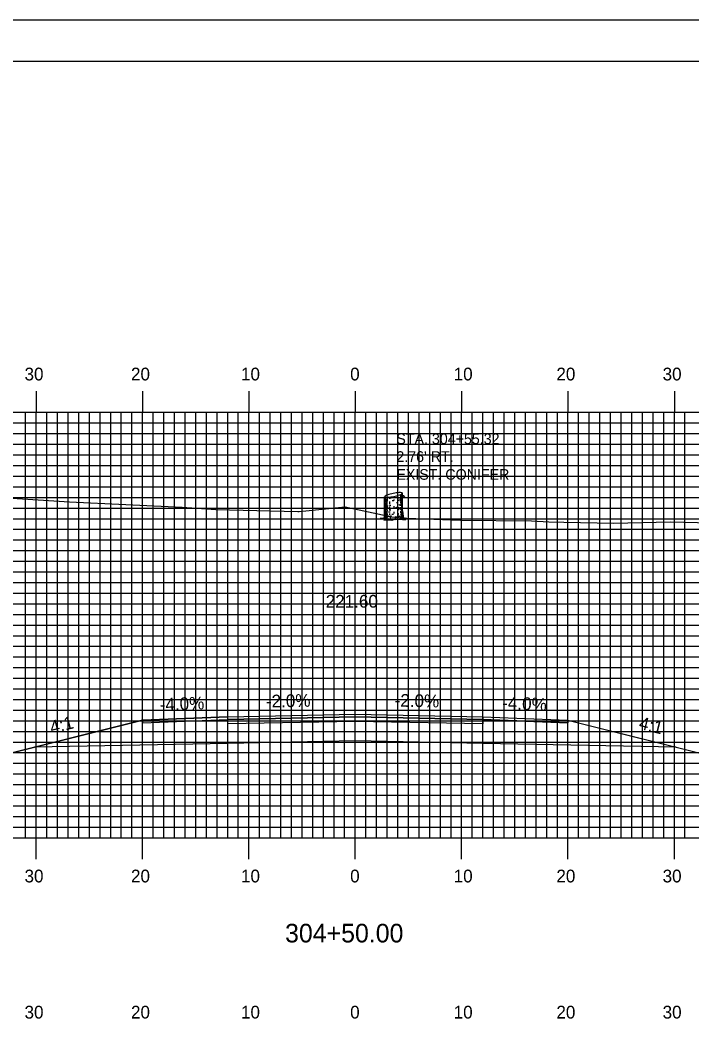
# Model space of a CAD drawing. Extents: x 1816489 to 1816833, y 442591 to 442811.
# Drawn here: x 1816623.6 to 1816686.7, y 442716.2 to 442810.5 of the extents above; entities that cross this region are included whole.
import ezdxf

# ---------------------------------------------------------------- set-up
doc = ezdxf.new("R2010")
doc.units = 0
for name, color, linetype in [('ANNOTATION', 7, 'Continuous'), ('BORDER', 7, 'Continuous'), ('D_Roadway_Centerline', 7, 'Continuous'), ('D_Roadway_Centerline_Text', 7, 'Continuous'), ('D_Roadway_Edge_Shoulder', 7, 'Continuous'), ('D_Roadway_Edge_TW', 7, 'Continuous'), ('D_Roadway_Pavement', 7, 'Continuous'), ('D_Roadway_SlopeLines', 7, 'Continuous'), ('D_Roadway_SubGrade', 7, 'Continuous'), ('D_Text_Monospaced', 7, 'Continuous'), ('H_V ANNOTATION', 7, 'Continuous'), ('M_Trees_Conifer_Pay', 7, 'Continuous'), ('MAJOR', 7, 'Continuous'), ('MINOR', 7, 'Continuous'), ('PLOT BOUNDARY', 7, 'Continuous'), ('S_Roadway_Centerline', 7, 'Continuous')]:
    doc.layers.add(name, color=color, linetype=linetype)

msp = doc.modelspace()

# ---------------------------------------------------------------- linework, layer by layer
at = {"layer": 'BORDER'}
msp.add_lwpolyline([(1816505.473, 442596.665), (1816825.473, 442596.665), (1816825.473, 442806.665), (1816505.473, 442806.665)], close=True, dxfattribs=at)
at = {"layer": 'D_Roadway_Centerline'}
msp.add_lwpolyline([(1816567.063, 442766.87), (1816568.313, 442766.776), (1816569.563, 442766.53), (1816570.813, 442766.133), (1816572.063, 442765.584), (1816620.899, 442741.166), (1816624.899, 442742.166), (1816635.073, 442744.709), (1816643.073, 442745.029), (1816655.073, 442745.269), (1816667.073, 442745.029), (1816675.073, 442744.709), (1816685.247, 442742.166), (1816689.247, 442741.166), (1816725.957, 442759.521), (1816727.207, 442760.056), (1816728.457, 442760.411), (1816729.707, 442760.586), (1816730.957, 442760.58)], dxfattribs=at)
at = {"layer": 'D_Roadway_Edge_Shoulder'}
for points in [[(1816643.073, 442745.029), (1816635.073, 442744.709), (1816635.073, 442744.459), (1816643.073, 442744.779)], [(1816667.073, 442745.029), (1816675.073, 442744.709), (1816675.073, 442744.459), (1816667.073, 442744.779)]]:
    msp.add_lwpolyline(points, close=True, dxfattribs=at)
at = {"layer": 'D_Roadway_Edge_TW'}
msp.add_lwpolyline([(1816643.073, 442744.779), (1816643.073, 442745.029), (1816655.073, 442745.269), (1816667.073, 442745.029), (1816667.073, 442744.779), (1816655.073, 442745.019)], close=True, dxfattribs=at)
at = {"layer": 'D_Roadway_Pavement'}
msp.add_lwpolyline([(1816643.073, 442744.362), (1816643.073, 442744.779), (1816655.073, 442745.019), (1816667.073, 442744.779), (1816667.073, 442744.362), (1816655.073, 442744.602)], close=True, dxfattribs=at)
at = {"layer": 'D_Roadway_SlopeLines'}
for points in [[(1816635.073, 442744.709), (1816620.899, 442741.166)], [(1816675.073, 442744.709), (1816689.247, 442741.166)]]:
    msp.add_lwpolyline(points, dxfattribs=at)
at = {"layer": 'D_Roadway_SubGrade'}
msp.add_lwpolyline([(1816643.073, 442742.529), (1816624.899, 442742.166), (1816635.073, 442744.709), (1816635.073, 442744.459), (1816643.073, 442744.779), (1816655.073, 442745.019), (1816667.073, 442744.779), (1816675.073, 442744.459), (1816675.073, 442744.709), (1816685.247, 442742.166), (1816667.073, 442742.529), (1816655.073, 442742.769)], close=True, dxfattribs=at)
at = {"layer": 'M_Trees_Conifer_Pay'}
for p, q in [((1816659.309, 442765.928), (1816659.309, 442765.705)), ((1816659.426, 442765.989), (1816659.426, 442765.827)), ((1816659.426, 442765.759), (1816659.426, 442765.631)), ((1816659.498, 442764.415), (1816659.498, 442766.062)), ((1816657.834, 442764.005), (1816657.834, 442765.726)), ((1816657.881, 442765.689), (1816657.881, 442765.218)), ((1816657.881, 442765.153), (1816657.881, 442764.845)), ((1816657.939, 442765.678), (1816657.939, 442765.58)), ((1816657.939, 442765.506), (1816657.939, 442765.302)), ((1816657.939, 442765.244), (1816657.939, 442765.045)), ((1816657.939, 442764.997), (1816657.939, 442764.661)), ((1816658.065, 442765.67), (1816658.065, 442765.438)), ((1816658.065, 442765.397), (1816658.065, 442765.323)), ((1816658.065, 442764.919), (1816658.065, 442764.781)), ((1816658.284, 442765.69), (1816658.284, 442765.522)), ((1816658.284, 442765.285), (1816658.284, 442765.048)), ((1816658.69, 442765.459), (1816658.69, 442765.363)), ((1816658.69, 442764.845), (1816658.69, 442764.771)), ((1816659.08, 442765.732), (1816659.08, 442765.533)), ((1816659.08, 442765.475), (1816659.08, 442765.386)), ((1816659.08, 442765.039), (1816659.08, 442764.934)), ((1816659.309, 442765.617), (1816659.309, 442765.569)), ((1816659.309, 442765.234), (1816659.309, 442765.102)), ((1816659.309, 442764.991), (1816659.309, 442764.882)), ((1816659.366, 442765.434), (1816659.315, 442765.374)), ((1816659.426, 442765.444), (1816659.426, 442765.108)), ((1816659.426, 442765.071), (1816659.426, 442764.909)), ((1816659.426, 442764.861), (1816659.426, 442764.645)), ((1816657.881, 442764.798), (1816657.881, 442764.306)), ((1816657.881, 442764.252), (1816657.881, 442764.005)), ((1816657.939, 442764.608), (1816657.939, 442764.472)), ((1816657.939, 442764.373), (1816657.939, 442763.995)), ((1816658.065, 442764.509), (1816658.065, 442764.367)), ((1816658.065, 442764.106), (1816658.065, 442764.011)), ((1816658.284, 442764.804), (1816658.284, 442764.651)), ((1816658.284, 442764.608), (1816658.284, 442764.435)), ((1816658.284, 442764.157), (1816658.284, 442764.005)), ((1816658.69, 442764.746), (1816658.69, 442764.598)), ((1816658.69, 442764.306), (1816658.69, 442764.153)), ((1816659.08, 442764.567), (1816659.08, 442764.421)), ((1816659.08, 442764.188), (1816659.08, 442764.1)), ((1816659.309, 442764.746), (1816659.309, 442764.604)), ((1816659.309, 442764.377), (1816659.309, 442764.205)), ((1816659.426, 442764.614), (1816659.426, 442764.54)), ((1816659.426, 442764.499), (1816659.426, 442764.326)), ((1816658.065, 442763.611), (1816658.227, 442763.675)), ((1816658.502, 442763.547), (1816658.376, 442763.611))]:
    msp.add_line(p, q, dxfattribs=at)
for points in [[(1816659.315, 442765.56), (1816659.351, 442765.485), (1816659.399, 442765.543), (1816659.456, 442765.611), (1816659.549, 442765.804), (1816659.613, 442765.852), (1816659.644, 442765.858)], [(1816659.329, 442765.306), (1816659.366, 442765.434), (1816659.429, 442765.549), (1816659.46, 442765.617), (1816659.529, 442765.763)], [(1816659.544, 442765.793), (1816659.619, 442765.8), (1816659.691, 442765.701)], [(1816658.013, 442765.032), (1816658.007, 442765.127), (1816658.05, 442765.104), (1816658.05, 442765.01)], [(1816659.281, 442765.522), (1816659.25, 442765.438), (1816659.246, 442765.37), (1816659.277, 442765.306)], [(1816659.498, 442764.415), (1816659.549, 442764.153), (1816659.565, 442763.879), (1816659.623, 442763.754), (1816659.759, 442763.723), (1816659.528, 442763.686), (1816659.528, 442763.686), (1816659.534, 442763.638), (1816659.782, 442763.544), (1816659.507, 442763.56), (1816659.152, 442763.581), (1816658.83, 442763.57), (1816658.837, 442763.653), (1816658.689, 442763.57), (1816658.502, 442763.547), (1816658.526, 442763.48), (1816658.258, 442763.523), (1816658.038, 442763.496), (1816657.745, 442763.513), (1816658.034, 442763.57), (1816658.065, 442763.611), (1816657.902, 442763.669), (1816657.665, 442763.68), (1816657.424, 442763.68), (1816657.766, 442763.737), (1816657.807, 442763.818), (1816657.834, 442764.005)], [(1816657.882, 442763.957), (1816657.861, 442763.879), (1816657.84, 442763.785)], [(1816657.96, 442763.937), (1816657.965, 442763.821), (1816657.912, 442763.733), (1816657.902, 442763.669)], [(1816658.122, 442763.964), (1816658.122, 442763.832), (1816658.034, 442763.733)], [(1816658.349, 442763.723), (1816658.416, 442763.818), (1816658.443, 442763.957)], [(1816658.837, 442763.653), (1816658.911, 442763.795), (1816658.921, 442763.896)], [(1816659.088, 442764.022), (1816659.098, 442763.896), (1816659.172, 442763.852)], [(1816659.152, 442764.633), (1816659.164, 442764.556), (1816659.212, 442764.567), (1816659.199, 442764.734)], [(1816659.366, 442763.632), (1816659.351, 442763.77), (1816659.277, 442763.9)], [(1816659.324, 442764.127), (1816659.399, 442764.022), (1816659.403, 442763.848), (1816659.528, 442763.686)], [(1816659.423, 442764.272), (1816659.429, 442764.127), (1816659.477, 442764.058), (1816659.487, 442763.859)]]:
    msp.add_lwpolyline(points, dxfattribs=at)
for centre, radius, start, end in [((1816657.909, 442765.701), 0.0817, 132.38868, 146.7194), ((1816658.023, 442765.576), 0.251, 124.2194, 132.38868), ((1816658.333, 442765.12), 0.802, 108.05939, 124.2194), ((1816659.689, 442760.959), 5.179, 101.7194, 108.05939), ((1816657.642, 442770.829), 5.179, 275.37941, 281.7194), ((1816659.689, 442760.959), 5.179, 95.37941, 101.7194), ((1816657.642, 442770.829), 5.179, 281.7194, 288.05939), ((1816659.279, 442765.317), 0.802, 79.2194, 95.37941), ((1816658.999, 442766.667), 0.802, 288.05939, 304.2194), ((1816659.167, 442766.375), 0.571, 284.43166, 292.41325), ((1816659.382, 442765.858), 0.251, 71.05013, 79.2194), ((1816659.309, 442766.212), 0.251, 304.2194, 312.38868), ((1816659.366, 442766.03), 0.172, 300, 311.25059), ((1816659.437, 442766.018), 0.0817, 56.7194, 71.05013), ((1816659.423, 442766.087), 0.0817, 312.38868, 326.7194), ((1816659.438, 442765.947), 0.0624, 311.25059, 330), ((1816659.438, 442765.793), 0.0624, 311.25059, 330), ((1816659.453, 442766.042), 0.0527, 46.92298, 56.7194), ((1816659.467, 442766.057), 0.0314, 34.2194, 46.92298), ((1816659.447, 442766.071), 0.0527, 326.7194, 336.51582), ((1816659.454, 442765.938), 0.0441, 330, 343.94846), ((1816659.454, 442765.784), 0.0441, 330, 343.94846), ((1816659.472, 442766.06), 0.0264, 23.40735, 34.2194), ((1816659.466, 442766.063), 0.0314, 336.51582, 349.2194), ((1816659.475, 442766.062), 0.0226, 11.7194, 23.40735), ((1816659.475, 442766.062), 0.0226, 0.03145, 11.7194), ((1816659.471, 442766.062), 0.0264, 349.2194, 0.03145), ((1816659.465, 442765.935), 0.0334, 343.94846, 354.21506), ((1816659.465, 442765.781), 0.0334, 343.94846, 354.21506), ((1816657.866, 442765.548), 0.0334, 163.94846, 180), ((1816657.866, 442765.548), 0.0334, 180, 196.05154), ((1816657.866, 442765.101), 0.0334, 163.94846, 180), ((1816657.866, 442765.101), 0.0334, 180, 196.05154), ((1816657.866, 442764.891), 0.0334, 163.94846, 180), ((1816657.866, 442764.891), 0.0334, 180, 196.05154), ((1816657.865, 442765.725), 0.0314, 156.51582, 169.2194), ((1816657.86, 442765.726), 0.0264, 169.2194, 180.03145), ((1816657.856, 442765.726), 0.0226, 180.03145, 191.7194), ((1816657.856, 442765.726), 0.0226, 191.7194, 203.40735), ((1816657.876, 442765.551), 0.0441, 196.05154, 210), ((1816657.876, 442765.104), 0.0441, 196.05154, 210), ((1816657.876, 442764.894), 0.0441, 196.05154, 210), ((1816657.885, 442765.717), 0.0527, 146.7194, 156.51582), ((1816657.86, 442765.728), 0.0264, 203.40735, 214.2194), ((1816657.864, 442765.73), 0.0314, 214.2194, 226.92298), ((1816657.892, 442765.56), 0.0624, 210, 228.74941), ((1816657.892, 442765.113), 0.0624, 210, 228.74941), ((1816657.892, 442764.903), 0.0624, 210, 228.74941), ((1816657.879, 442765.746), 0.0527, 226.92298, 236.7194), ((1816657.894, 442765.77), 0.0817, 236.7194, 251.05013), ((1816657.964, 442765.643), 0.172, 228.74941, 240), ((1816657.964, 442765.196), 0.172, 228.74941, 240), ((1816657.964, 442764.986), 0.172, 228.74941, 240), ((1816657.949, 442765.93), 0.251, 251.05013, 259.2194), ((1816658.164, 442765.988), 0.571, 240, 240.33672), ((1816658.164, 442765.541), 0.571, 240, 240.33672), ((1816658.164, 442765.331), 0.571, 240, 246.85973), ((1816658.165, 442765.777), 0.571, 240, 247.05866), ((1816658.052, 442766.471), 0.802, 259.2194, 275.37941), ((1816658.164, 442765.988), 0.571, 246.85973, 257.98457), ((1816658.664, 442769.059), 4.124, 264.08098, 266.66759), ((1816658.666, 442769.738), 4.124, 264.6955, 266.73309), ((1816658.664, 442769.505), 4.124, 268.07512, 270), ((1816658.664, 442769.505), 4.124, 270, 270.35814), ((1816658.666, 442769.294), 4.124, 273.70524, 275.95043), ((1816658.664, 442769.505), 4.124, 275.78493, 277.05584), ((1816658.666, 442769.738), 4.124, 276.23804, 278.1032), ((1816658.664, 442769.059), 4.124, 277.61247, 278.1032), ((1816659.165, 442765.541), 0.571, 278.1032, 286.92962), ((1816659.167, 442766.221), 0.571, 278.1032, 284.36665), ((1816659.167, 442765.777), 0.571, 284.44928, 297.04285), ((1816659.167, 442766.221), 0.571, 297.0237, 300), ((1816659.165, 442765.541), 0.571, 297.18959, 300), ((1816659.165, 442765.331), 0.571, 297.18959, 300), ((1816659.364, 442765.196), 0.172, 300, 311.25059), ((1816659.364, 442764.986), 0.172, 300, 311.25059), ((1816659.366, 442765.876), 0.172, 300, 311.25059), ((1816659.437, 442765.113), 0.0624, 311.25059, 330), ((1816659.437, 442764.903), 0.0624, 311.25059, 330), ((1816659.453, 442765.104), 0.0441, 330, 343.94846), ((1816659.453, 442764.894), 0.0441, 330, 343.94846), ((1816659.463, 442765.101), 0.0334, 343.94846, 354.21506), ((1816659.463, 442764.891), 0.0334, 343.94846, 354.21506), ((1816659.464, 442765.337), 0.0334, 343.94846, 354.21506), ((1816657.866, 442764.654), 0.0334, 163.94846, 180), ((1816657.866, 442764.654), 0.0334, 180, 196.05154), ((1816657.866, 442764.457), 0.0334, 163.94846, 180), ((1816657.866, 442764.261), 0.0334, 163.94846, 180), ((1816657.866, 442764.261), 0.0334, 180, 196.05154), ((1816657.866, 442764.041), 0.0334, 163.94846, 180), ((1816657.866, 442764.041), 0.0334, 180, 196.05154), ((1816657.876, 442764.657), 0.0441, 196.05154, 210), ((1816657.876, 442764.264), 0.0441, 196.05154, 210), ((1816657.876, 442764.044), 0.0441, 196.05154, 210), ((1816657.892, 442764.667), 0.0624, 210, 228.74941), ((1816657.892, 442764.273), 0.0624, 210, 228.74941), ((1816657.892, 442764.053), 0.0624, 210, 228.74941), ((1816657.964, 442764.749), 0.172, 228.74941, 240), ((1816657.964, 442764.356), 0.172, 228.74941, 240), ((1816657.964, 442764.136), 0.172, 228.74941, 240), ((1816658.164, 442765.094), 0.571, 240, 246.85973), ((1816658.153, 442764.903), 0.571, 241.23686, 248.02677), ((1816658.164, 442764.701), 0.571, 240, 246.85973), ((1816658.164, 442764.481), 0.571, 240, 244.53138), ((1816658.164, 442765.331), 0.571, 259.27072, 261.8968), ((1816658.664, 442768.849), 4.124, 261.8968, 263.14738), ((1816658.664, 442767.998), 4.124, 262.44379, 263.51202), ((1816658.664, 442768.414), 4.124, 263.49906, 265.83975), ((1816658.664, 442768.612), 4.124, 264.71603, 266.31934), ((1816658.664, 442768.219), 4.124, 267.81166, 270), ((1816658.664, 442768.849), 4.124, 270, 270.35814), ((1816658.664, 442768.219), 4.124, 270, 270.13279), ((1816658.664, 442768.849), 4.124, 273.14934, 275.45691), ((1816658.664, 442768.219), 4.124, 275.78493, 276.78961), ((1816658.664, 442767.998), 4.124, 277.36842, 278.1032), ((1816659.165, 442764.481), 0.571, 278.1032, 281.63703), ((1816659.165, 442765.094), 0.571, 285.39827, 297.18959), ((1816659.165, 442764.701), 0.571, 288.50673, 297.27208), ((1816659.165, 442764.897), 0.571, 289.29072, 300), ((1816659.364, 442764.552), 0.172, 300, 311.25059), ((1816659.364, 442764.136), 0.172, 300, 311.25059), ((1816659.437, 442764.469), 0.0624, 311.25059, 330), ((1816659.437, 442764.053), 0.0624, 311.25059, 330), ((1816659.453, 442764.46), 0.0441, 330, 343.94846), ((1816659.453, 442764.044), 0.0441, 330, 343.94846), ((1816659.463, 442764.457), 0.0334, 343.94846, 354.21506), ((1816659.463, 442764.041), 0.0334, 343.94846, 354.21506)]:
    msp.add_arc(centre, radius, start, end, dxfattribs=at)
at = {"layer": 'MAJOR'}
for p, q in [((1816625.073, 442775.669), (1816625.073, 442773.665)), ((1816635.073, 442775.669), (1816635.073, 442773.665)), ((1816645.073, 442775.669), (1816645.073, 442773.665)), ((1816655.073, 442775.669), (1816655.073, 442773.665)), ((1816665.073, 442775.669), (1816665.073, 442773.665)), ((1816675.073, 442775.669), (1816675.073, 442773.665)), ((1816685.073, 442775.669), (1816685.073, 442773.665)), ((1816515.073, 442773.665), (1816795.073, 442773.665)), ((1816515.073, 442773.665), (1816795.073, 442773.665)), ((1816625.073, 442733.665), (1816625.073, 442773.665)), ((1816635.073, 442733.665), (1816635.073, 442773.665)), ((1816645.073, 442733.665), (1816645.073, 442773.665)), ((1816655.073, 442733.665), (1816655.073, 442773.665)), ((1816665.073, 442733.665), (1816665.073, 442773.665)), ((1816675.073, 442733.665), (1816675.073, 442773.665)), ((1816685.073, 442733.665), (1816685.073, 442773.665)), ((1816515.073, 442768.665), (1816795.073, 442768.665)), ((1816515.073, 442763.665), (1816795.073, 442763.665)), ((1816515.073, 442758.665), (1816795.073, 442758.665)), ((1816515.073, 442753.665), (1816795.073, 442753.665)), ((1816515.073, 442748.665), (1816795.073, 442748.665)), ((1816515.073, 442743.665), (1816795.073, 442743.665)), ((1816515.073, 442738.665), (1816795.073, 442738.665)), ((1816515.073, 442733.665), (1816795.073, 442733.665)), ((1816515.073, 442733.665), (1816795.073, 442733.665)), ((1816625.073, 442731.661), (1816625.073, 442733.665)), ((1816635.073, 442731.661), (1816635.073, 442733.665)), ((1816645.073, 442731.661), (1816645.073, 442733.665)), ((1816655.073, 442731.661), (1816655.073, 442733.665)), ((1816665.073, 442731.661), (1816665.073, 442733.665)), ((1816675.073, 442731.661), (1816675.073, 442733.665)), ((1816685.073, 442731.661), (1816685.073, 442733.665))]:
    msp.add_line(p, q, dxfattribs=at)
at = {"layer": 'MINOR'}
for p, q in [((1816624.073, 442733.665), (1816624.073, 442773.665)), ((1816626.073, 442733.665), (1816626.073, 442773.665)), ((1816627.073, 442733.665), (1816627.073, 442773.665)), ((1816628.073, 442733.665), (1816628.073, 442773.665)), ((1816629.073, 442733.665), (1816629.073, 442773.665)), ((1816630.073, 442733.665), (1816630.073, 442773.665)), ((1816631.073, 442733.665), (1816631.073, 442773.665)), ((1816632.073, 442733.665), (1816632.073, 442773.665)), ((1816633.073, 442733.665), (1816633.073, 442773.665)), ((1816634.073, 442733.665), (1816634.073, 442773.665)), ((1816636.073, 442733.665), (1816636.073, 442773.665)), ((1816637.073, 442733.665), (1816637.073, 442773.665)), ((1816638.073, 442733.665), (1816638.073, 442773.665)), ((1816639.073, 442733.665), (1816639.073, 442773.665)), ((1816640.073, 442733.665), (1816640.073, 442773.665)), ((1816641.073, 442733.665), (1816641.073, 442773.665)), ((1816642.073, 442733.665), (1816642.073, 442773.665)), ((1816643.073, 442733.665), (1816643.073, 442773.665)), ((1816644.073, 442733.665), (1816644.073, 442773.665)), ((1816646.073, 442733.665), (1816646.073, 442773.665)), ((1816647.073, 442733.665), (1816647.073, 442773.665)), ((1816648.073, 442733.665), (1816648.073, 442773.665)), ((1816649.073, 442733.665), (1816649.073, 442773.665)), ((1816650.073, 442733.665), (1816650.073, 442773.665)), ((1816651.073, 442733.665), (1816651.073, 442773.665)), ((1816652.073, 442733.665), (1816652.073, 442773.665)), ((1816653.073, 442733.665), (1816653.073, 442773.665)), ((1816654.073, 442733.665), (1816654.073, 442773.665)), ((1816656.073, 442733.665), (1816656.073, 442773.665)), ((1816657.073, 442733.665), (1816657.073, 442773.665)), ((1816658.073, 442733.665), (1816658.073, 442773.665)), ((1816659.073, 442733.665), (1816659.073, 442773.665)), ((1816660.073, 442733.665), (1816660.073, 442773.665)), ((1816661.073, 442733.665), (1816661.073, 442773.665)), ((1816662.073, 442733.665), (1816662.073, 442773.665)), ((1816663.073, 442733.665), (1816663.073, 442773.665)), ((1816664.073, 442733.665), (1816664.073, 442773.665)), ((1816666.073, 442733.665), (1816666.073, 442773.665)), ((1816667.073, 442733.665), (1816667.073, 442773.665)), ((1816668.073, 442733.665), (1816668.073, 442773.665)), ((1816669.073, 442733.665), (1816669.073, 442773.665)), ((1816670.073, 442733.665), (1816670.073, 442773.665)), ((1816671.073, 442733.665), (1816671.073, 442773.665)), ((1816672.073, 442733.665), (1816672.073, 442773.665)), ((1816673.073, 442733.665), (1816673.073, 442773.665)), ((1816674.073, 442733.665), (1816674.073, 442773.665)), ((1816676.073, 442733.665), (1816676.073, 442773.665)), ((1816677.073, 442733.665), (1816677.073, 442773.665)), ((1816678.073, 442733.665), (1816678.073, 442773.665)), ((1816679.073, 442733.665), (1816679.073, 442773.665)), ((1816680.073, 442733.665), (1816680.073, 442773.665)), ((1816681.073, 442733.665), (1816681.073, 442773.665)), ((1816682.073, 442733.665), (1816682.073, 442773.665)), ((1816683.073, 442733.665), (1816683.073, 442773.665)), ((1816684.073, 442733.665), (1816684.073, 442773.665)), ((1816686.073, 442733.665), (1816686.073, 442773.665)), ((1816515.073, 442772.665), (1816795.073, 442772.665)), ((1816515.073, 442771.665), (1816795.073, 442771.665)), ((1816515.073, 442770.665), (1816795.073, 442770.665)), ((1816515.073, 442769.665), (1816795.073, 442769.665)), ((1816515.073, 442767.665), (1816795.073, 442767.665)), ((1816515.073, 442766.665), (1816795.073, 442766.665)), ((1816515.073, 442765.665), (1816795.073, 442765.665)), ((1816515.073, 442764.665), (1816795.073, 442764.665)), ((1816515.073, 442762.665), (1816795.073, 442762.665)), ((1816515.073, 442761.665), (1816795.073, 442761.665)), ((1816515.073, 442760.665), (1816795.073, 442760.665)), ((1816515.073, 442759.665), (1816795.073, 442759.665)), ((1816515.073, 442757.665), (1816795.073, 442757.665)), ((1816515.073, 442756.665), (1816795.073, 442756.665)), ((1816515.073, 442755.665), (1816795.073, 442755.665)), ((1816515.073, 442754.665), (1816795.073, 442754.665)), ((1816515.073, 442752.665), (1816795.073, 442752.665)), ((1816515.073, 442751.665), (1816795.073, 442751.665)), ((1816515.073, 442750.665), (1816795.073, 442750.665)), ((1816515.073, 442749.665), (1816795.073, 442749.665)), ((1816515.073, 442747.665), (1816795.073, 442747.665)), ((1816515.073, 442746.665), (1816795.073, 442746.665)), ((1816515.073, 442745.665), (1816795.073, 442745.665)), ((1816515.073, 442744.665), (1816795.073, 442744.665)), ((1816515.073, 442742.665), (1816795.073, 442742.665)), ((1816515.073, 442741.665), (1816795.073, 442741.665)), ((1816515.073, 442740.665), (1816795.073, 442740.665)), ((1816515.073, 442739.665), (1816795.073, 442739.665)), ((1816515.073, 442737.665), (1816795.073, 442737.665)), ((1816515.073, 442736.665), (1816795.073, 442736.665)), ((1816515.073, 442735.665), (1816795.073, 442735.665)), ((1816515.073, 442734.665), (1816795.073, 442734.665))]:
    msp.add_line(p, q, dxfattribs=at)
at = {"layer": 'PLOT BOUNDARY'}
msp.add_lwpolyline([(1816489.286, 442590.547), (1816829.286, 442590.547), (1816829.286, 442810.547), (1816489.286, 442810.547)], close=True, dxfattribs=at)
at = {"layer": 'S_Roadway_Centerline'}
msp.add_lwpolyline([(1816622.294, 442765.621), (1816628.188, 442765.242), (1816638.778, 442764.738), (1816641.95, 442764.533), (1816649.681, 442764.347), (1816649.803, 442764.347), (1816654.11, 442764.791), (1816658.509, 442763.847), (1816659.912, 442763.726), (1816664.971, 442763.536), (1816671.641, 442763.46), (1816673.279, 442763.367), (1816674.67, 442763.341), (1816679.389, 442763.238), (1816684.667, 442763.381), (1816688.535, 442763.288)], dxfattribs=at)

# ---------------------------------------------------------------- texts
at = {"layer": 'ANNOTATION'}
for s, rotation, p in [('-4.0%', 2.29061, (1816636.705, 442745.576)), ('-2.0%', 1.14576, (1816646.679, 442745.902)), ('-2.0%', 358.85424, (1816658.759, 442745.996)), ('-4.0%', 357.70939, (1816668.865, 442745.759)), ('4:1', 14.03624, (1816626.522, 442743.433)), ('4:1', 345.96376, (1816681.666, 442743.922))]:
    msp.add_text(s, height=1.2, rotation=rotation, dxfattribs=at).set_placement(p)
at = {"layer": 'D_Roadway_Centerline'}
for s, p in [('C', (1816655.068, 442745.269)), ('L', (1816655.073, 442745.262))]:
    msp.add_text(s, height=0.0146, dxfattribs=at).set_placement(p)
at = {"layer": 'D_Roadway_Centerline_Text'}
msp.add_text('221.60', height=1.2, dxfattribs=at).set_placement((1816652.29, 442755.299))
at = {"layer": 'D_Text_Monospaced'}
for s, height, p in [('STA. 304+55.32', 0.99996, (1816658.934, 442770.674)), ("2.76' RT.", 1, (1816658.934, 442769.006)), ('EXIST. CONIFER', 0.99996, (1816658.934, 442767.326))]:
    msp.add_text(s, height=height, dxfattribs=at).set_placement(p)
at = {"layer": 'H_V ANNOTATION'}
for s, height, p in [('30', 1.2, (1816623.97, 442776.665)), ('20', 1.2, (1816633.981, 442776.665)), ('10', 1.2, (1816644.324, 442776.665)), ('0', 1.2, (1816654.591, 442776.665)), ('10', 1.2, (1816664.324, 442776.665)), ('20', 1.2, (1816673.981, 442776.665)), ('30', 1.2, (1816683.97, 442776.665)), ('30', 1.2, (1816623.97, 442729.465)), ('20', 1.2, (1816633.981, 442729.465)), ('10', 1.2, (1816644.324, 442729.465)), ('0', 1.2, (1816654.591, 442729.465)), ('10', 1.2, (1816664.324, 442729.465)), ('20', 1.2, (1816673.981, 442729.465)), ('30', 1.2, (1816683.97, 442729.465)), ('304+50.00', 1.75, (1816648.471, 442723.821)), ('30', 1.2, (1816623.97, 442716.665)), ('20', 1.2, (1816633.981, 442716.665)), ('10', 1.2, (1816644.324, 442716.665)), ('0', 1.2, (1816654.591, 442716.665)), ('10', 1.2, (1816664.324, 442716.665)), ('20', 1.2, (1816673.981, 442716.665)), ('30', 1.2, (1816683.97, 442716.665))]:
    msp.add_text(s, height=height, dxfattribs=at).set_placement(p)

doc.saveas('drawing.dxf')
